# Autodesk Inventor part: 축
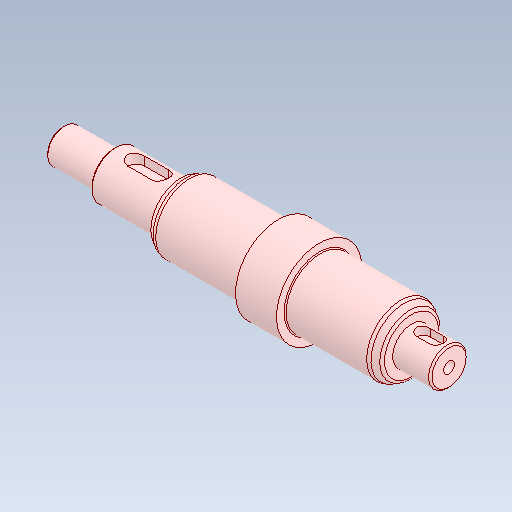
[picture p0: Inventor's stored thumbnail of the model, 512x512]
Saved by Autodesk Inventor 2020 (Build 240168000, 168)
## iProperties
Created: 2024-04
Part Number: 축
Material: 강철, 연강
Document SubType Name: Modeling
Designer: oem
Density: 7.86 g/cm^3
Appearance: 기본값
Mass: 220.622 g
Surface Area: 71.3922 cm^2
Volume: 28.069 cm^3
Sending System: Autodesk Inventor 2025
Preprocessor: ST-DEVELOPER v20
Author: jhkim
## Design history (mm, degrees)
feature "솔리드1"
node "솔리드2"
